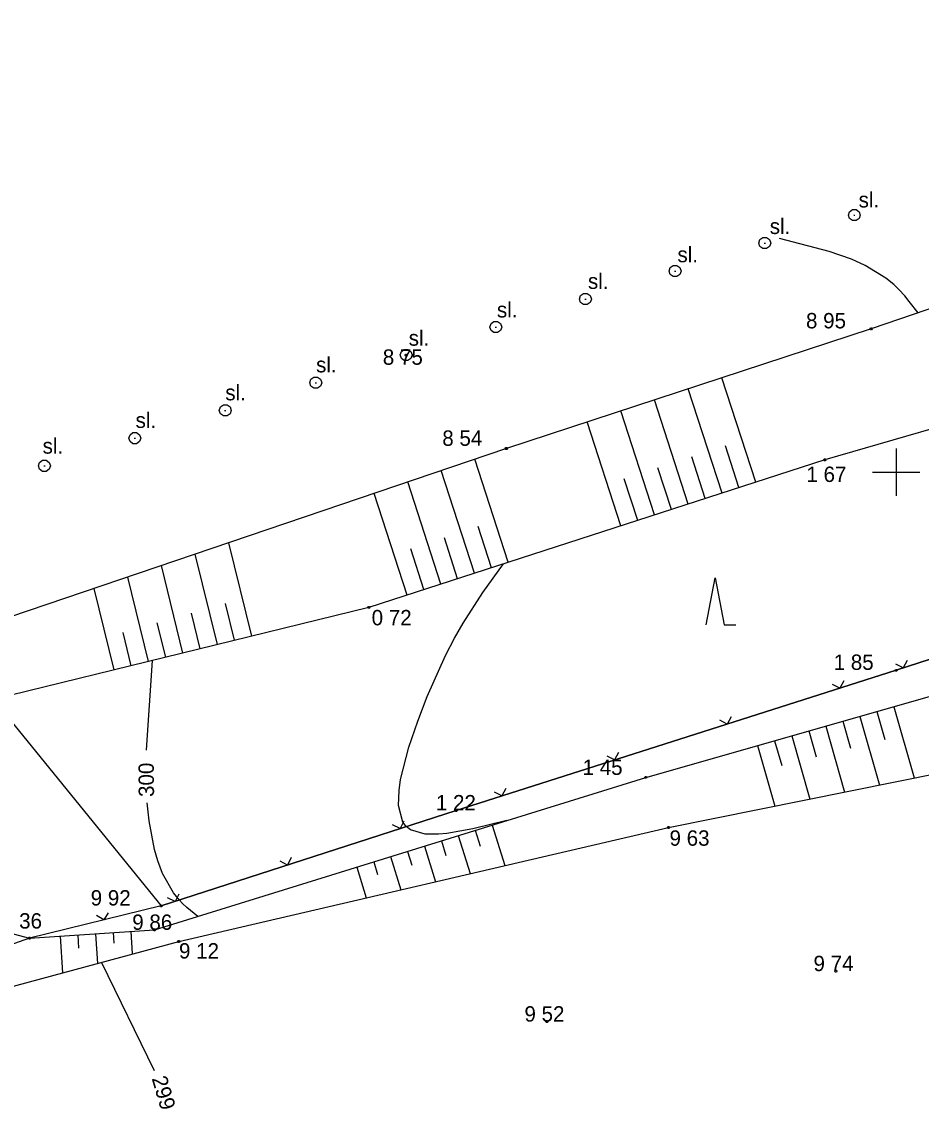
# Model space of a CAD drawing. Extents: x -684336 to -684039, y -993109 to -992688.
# Drawn here: x -684236.99 to -684198.94, y -992826.95 to -992780.95 of the extents above; entities that cross this region are included whole.
import ezdxf

# ---------------------------------------------------------------- set-up
doc = ezdxf.new("R2010")
doc.units = 0
for name, color, linetype in [('51', 7, 'Continuous'), ('53', 7, 'Continuous'), ('55', 7, 'Continuous'), ('56', 7, 'Continuous'), ('57', 7, 'Continuous'), ('60', 7, 'Continuous'), ('70', 7, 'Continuous'), ('81', 7, 'Continuous')]:
    doc.layers.add(name, color=color, linetype=linetype)

msp = doc.modelspace()

# ---------------------------------------------------------------- linework, layer by layer
at = {"layer": '51'}
for points in [[(-684153.498, -992795.02), (-684158.4, -992796.16), (-684158.08, -992789.98), (-684162.97, -992785.34), (-684173.37, -992785.88), (-684187.14, -992789.19), (-684201.06, -992793.94), (-684216.49, -992799), (-684239.84, -992806.93)], [(-684155.696, -992787.999), (-684158.08, -992789.98), (-684161.21, -992793.24), (-684163.83, -992796.06), (-684166.91, -992797.89), (-684183.05, -992802.89), (-684200, -992808.38), (-684218.61, -992814.31), (-684231.09, -992818.35), (-684236.66, -992819.71), (-684248.11, -992823.77)], [(-684161.21, -992793.24), (-684163.51, -992789.57), (-684179.03, -992792.54), (-684203.02, -992799.48), (-684222.3, -992805.72), (-684238.2, -992809.62), (-684250.775, -992812.098)], [(-684251.105, -992813.042), (-684244.68, -992817.58), (-684236.66, -992819.71), (-684231.37, -992819.36), (-684210.59, -992812.91), (-684194.44, -992808.31), (-684190.16, -992807.38), (-684180.44, -992804.41), (-684173.82, -992803.72), (-684160.95, -992797.464)], [(-684242.63, -992823.16), (-684230.34, -992819.85), (-684209.63, -992815.03), (-684188.57, -992810.79), (-684181.93, -992807.38), (-684170.95, -992804.67), (-684162.34, -992803.75), (-684152.61, -992807.1), (-684146.61, -992817.325)], [(-684199.538, -992807.967), (-684199.699, -992808.282), (-684200.013, -992808.122)], [(-684202.22, -992808.825), (-684202.382, -992809.139), (-684202.696, -992808.977)], [(-684206.984, -992810.343), (-684207.146, -992810.657), (-684207.46, -992810.495)], [(-684211.748, -992811.861), (-684211.91, -992812.175), (-684212.224, -992812.013)], [(-684216.512, -992813.379), (-684216.674, -992813.693), (-684216.988, -992813.531)], [(-684220.828, -992814.765), (-684220.988, -992815.08), (-684221.303, -992814.919)], [(-684225.585, -992816.305), (-684225.745, -992816.62), (-684226.06, -992816.459)], [(-684230.342, -992817.845), (-684230.502, -992818.16), (-684230.817, -992817.999)], [(-684233.335, -992818.641), (-684233.519, -992818.943), (-684233.821, -992818.759)]]:
    msp.add_lwpolyline(points, dxfattribs=at)
at = {"layer": '53'}
for points in [[(-684200, -992799), (-684200, -992801)], [(-684201, -992800), (-684199, -992800)]]:
    msp.add_lwpolyline(points, dxfattribs=at)
at = {"layer": '55'}
for points in [[(-684201.692, -992788.893), (-684201.567, -992788.983), (-684201.517, -992789.128), (-684201.567, -992789.273), (-684201.692, -992789.363), (-684201.847, -992789.363), (-684201.972, -992789.273), (-684202.022, -992789.128), (-684201.972, -992788.983), (-684201.847, -992788.893)], [(-684205.483, -992790.077), (-684205.358, -992790.167), (-684205.308, -992790.312), (-684205.358, -992790.457), (-684205.483, -992790.547), (-684205.638, -992790.547), (-684205.763, -992790.457), (-684205.813, -992790.312), (-684205.763, -992790.167), (-684205.638, -992790.077)], [(-684209.275, -992791.26), (-684209.15, -992791.35), (-684209.1, -992791.495), (-684209.15, -992791.64), (-684209.275, -992791.73), (-684209.43, -992791.73), (-684209.555, -992791.64), (-684209.605, -992791.495), (-684209.555, -992791.35), (-684209.43, -992791.26)], [(-684213.067, -992792.443), (-684212.942, -992792.533), (-684212.892, -992792.678), (-684212.942, -992792.823), (-684213.067, -992792.913), (-684213.222, -992792.913), (-684213.347, -992792.823), (-684213.397, -992792.678), (-684213.347, -992792.533), (-684213.222, -992792.443)], [(-684216.858, -992793.627), (-684216.733, -992793.717), (-684216.683, -992793.862), (-684216.733, -992794.007), (-684216.858, -992794.097), (-684217.013, -992794.097), (-684217.138, -992794.007), (-684217.188, -992793.862), (-684217.138, -992793.717), (-684217.013, -992793.627)], [(-684220.65, -992794.81), (-684220.525, -992794.9), (-684220.475, -992795.045), (-684220.525, -992795.19), (-684220.65, -992795.28), (-684220.805, -992795.28), (-684220.93, -992795.19), (-684220.98, -992795.045), (-684220.93, -992794.9), (-684220.805, -992794.81)], [(-684224.476, -992795.982), (-684224.351, -992796.072), (-684224.301, -992796.217), (-684224.351, -992796.362), (-684224.476, -992796.452), (-684224.631, -992796.452), (-684224.756, -992796.362), (-684224.806, -992796.217), (-684224.756, -992796.072), (-684224.631, -992795.982)], [(-684228.302, -992797.154), (-684228.177, -992797.244), (-684228.127, -992797.389), (-684228.177, -992797.534), (-684228.302, -992797.624), (-684228.457, -992797.624), (-684228.582, -992797.534), (-684228.632, -992797.389), (-684228.582, -992797.244), (-684228.457, -992797.154)], [(-684232.128, -992798.326), (-684232.003, -992798.416), (-684231.953, -992798.561), (-684232.003, -992798.706), (-684232.128, -992798.796), (-684232.283, -992798.796), (-684232.408, -992798.706), (-684232.458, -992798.561), (-684232.408, -992798.416), (-684232.283, -992798.326)], [(-684235.954, -992799.498), (-684235.829, -992799.588), (-684235.779, -992799.733), (-684235.829, -992799.878), (-684235.954, -992799.968), (-684236.109, -992799.968), (-684236.234, -992799.878), (-684236.284, -992799.733), (-684236.234, -992799.588), (-684236.109, -992799.498)]]:
    msp.add_lwpolyline(points, close=True, dxfattribs=at)
for points in [[(-684201.797, -992789.133), (-684201.742, -992789.133)], [(-684205.588, -992790.317), (-684205.533, -992790.317)], [(-684209.38, -992791.5), (-684209.325, -992791.5)], [(-684213.172, -992792.683), (-684213.117, -992792.683)], [(-684216.963, -992793.867), (-684216.908, -992793.867)], [(-684220.755, -992795.05), (-684220.7, -992795.05)], [(-684224.581, -992796.222), (-684224.526, -992796.222)], [(-684228.407, -992797.394), (-684228.352, -992797.394)], [(-684232.233, -992798.566), (-684232.178, -992798.566)], [(-684236.059, -992799.738), (-684236.004, -992799.738)]]:
    msp.add_lwpolyline(points, dxfattribs=at)
at = {"layer": '57'}
for points in [[(-684201.038, -992793.902), (-684201.015, -992793.94), (-684201.038, -992793.977), (-684201.083, -992793.977), (-684201.105, -992793.94), (-684201.083, -992793.902)], [(-684220.708, -992795.013), (-684220.685, -992795.05), (-684220.708, -992795.088), (-684220.753, -992795.088), (-684220.775, -992795.05), (-684220.753, -992795.013)], [(-684216.468, -992798.963), (-684216.445, -992799), (-684216.468, -992799.037), (-684216.513, -992799.037), (-684216.535, -992799), (-684216.513, -992798.963)], [(-684202.998, -992799.443), (-684202.975, -992799.48), (-684202.998, -992799.518), (-684203.042, -992799.518), (-684203.065, -992799.48), (-684203.042, -992799.443)], [(-684222.278, -992805.682), (-684222.255, -992805.72), (-684222.278, -992805.758), (-684222.323, -992805.758), (-684222.345, -992805.72), (-684222.323, -992805.682)], [(-684199.978, -992808.343), (-684199.955, -992808.38), (-684199.978, -992808.417), (-684200.022, -992808.417), (-684200.045, -992808.38), (-684200.022, -992808.343)], [(-684210.568, -992812.873), (-684210.545, -992812.91), (-684210.568, -992812.948), (-684210.613, -992812.948), (-684210.635, -992812.91), (-684210.613, -992812.873)], [(-684218.588, -992814.273), (-684218.565, -992814.31), (-684218.588, -992814.348), (-684218.633, -992814.348), (-684218.655, -992814.31), (-684218.633, -992814.273)], [(-684209.608, -992814.992), (-684209.585, -992815.03), (-684209.608, -992815.068), (-684209.653, -992815.068), (-684209.675, -992815.03), (-684209.653, -992814.992)], [(-684231.068, -992818.312), (-684231.045, -992818.35), (-684231.068, -992818.388), (-684231.113, -992818.388), (-684231.135, -992818.35), (-684231.113, -992818.312)], [(-684236.638, -992819.672), (-684236.615, -992819.71), (-684236.638, -992819.747), (-684236.682, -992819.747), (-684236.705, -992819.71), (-684236.682, -992819.672)], [(-684231.347, -992819.323), (-684231.325, -992819.36), (-684231.347, -992819.397), (-684231.392, -992819.397), (-684231.415, -992819.36), (-684231.392, -992819.323)], [(-684230.318, -992819.812), (-684230.295, -992819.85), (-684230.318, -992819.888), (-684230.363, -992819.888), (-684230.385, -992819.85), (-684230.363, -992819.812)], [(-684202.531, -992821.069), (-684202.508, -992821.106), (-684202.531, -992821.144), (-684202.576, -992821.144), (-684202.598, -992821.106), (-684202.576, -992821.069)], [(-684214.758, -992823.202), (-684214.735, -992823.24), (-684214.758, -992823.277), (-684214.802, -992823.277), (-684214.825, -992823.24), (-684214.802, -992823.202)]]:
    msp.add_lwpolyline(points, close=True, dxfattribs=at)
at = {"layer": '60'}
for points in [[(-684289.52, -992807.91), (-684276.43, -992803.58), (-684264.11, -992808.42), (-684259.07, -992805.67), (-684239.84, -992806.93), (-684238.2, -992809.62), (-684231.09, -992818.35), (-684218.61, -992814.31), (-684200, -992808.38), (-684183.05, -992802.89), (-684179.03, -992792.54), (-684175.03, -992780.95)], [(-684208.032, -992806.465), (-684207.657, -992804.465), (-684207.282, -992806.465), (-684206.782, -992806.465)]]:
    msp.add_lwpolyline(points, dxfattribs=at)
at = {"layer": '70'}
for points in [[(-684205.939, -992800.425), (-684207.368, -992796.009)], [(-684207.366, -992800.887), (-684208.793, -992796.476)], [(-684208.793, -992801.348), (-684210.219, -992796.943)], [(-684210.22, -992801.81), (-684211.644, -992797.411)], [(-684211.647, -992802.272), (-684213.069, -992797.878)], [(-684206.652, -992800.656), (-684207.224, -992798.89)], [(-684216.409, -992803.813), (-684217.821, -992799.452)], [(-684208.079, -992801.118), (-684208.65, -992799.354)], [(-684217.836, -992804.275), (-684219.241, -992799.934)], [(-684209.507, -992801.579), (-684210.077, -992799.818)], [(-684219.263, -992804.737), (-684220.662, -992800.417)], [(-684210.934, -992802.041), (-684211.503, -992800.283)], [(-684220.691, -992805.199), (-684222.082, -992800.899)], [(-684217.123, -992804.044), (-684217.686, -992802.304)], [(-684227.256, -992806.936), (-684228.225, -992802.985)], [(-684218.55, -992804.506), (-684219.111, -992802.774)], [(-684228.713, -992807.293), (-684229.651, -992803.47)], [(-684219.977, -992804.968), (-684220.535, -992803.244)], [(-684230.17, -992807.65), (-684231.076, -992803.954)], [(-684231.626, -992808.008), (-684232.502, -992804.438)], [(-684233.083, -992808.365), (-684233.928, -992804.922)], [(-684227.984, -992807.114), (-684228.366, -992805.56)], [(-684230.898, -992807.829), (-684231.254, -992806.376)], [(-684229.441, -992807.472), (-684229.81, -992805.968)], [(-684232.355, -992808.186), (-684232.699, -992806.784)], [(-684200.092, -992809.92), (-684199.232, -992812.937)], [(-684202.256, -992810.536), (-684201.931, -992811.675)], [(-684201.534, -992810.331), (-684200.707, -992813.234)], [(-684200.813, -992810.125), (-684200.476, -992811.309)], [(-684203.698, -992810.947), (-684203.387, -992812.04)], [(-684202.977, -992810.742), (-684202.182, -992813.531)], [(-684205.141, -992811.358), (-684204.843, -992812.405)], [(-684204.419, -992811.152), (-684203.658, -992813.828)], [(-684205.862, -992811.563), (-684205.133, -992814.125)], [(-684217.804, -992815.149), (-684217.598, -992815.815)], [(-684217.088, -992814.927), (-684216.556, -992816.642)], [(-684219.237, -992815.594), (-684219.043, -992816.218)], [(-684218.521, -992815.372), (-684218.021, -992816.983)], [(-684220.67, -992816.039), (-684220.489, -992816.621)], [(-684219.953, -992815.816), (-684219.485, -992817.324)], [(-684222.102, -992816.483), (-684221.934, -992817.024)], [(-684221.386, -992816.261), (-684220.95, -992817.665)], [(-684222.818, -992816.706), (-684222.415, -992818.006)], [(-684235.369, -992819.625), (-684235.266, -992821.177)], [(-684234.621, -992819.575), (-684234.583, -992820.136)], [(-684233.872, -992819.526), (-684233.789, -992820.779)], [(-684233.124, -992819.476), (-684233.095, -992819.918)], [(-684232.375, -992819.427), (-684232.312, -992820.381)]]:
    msp.add_lwpolyline(points, dxfattribs=at)
at = {"layer": '81'}
for points in [[(-684199.071, -992793.261), (-684199.444, -992792.779), (-684199.638, -992792.546), (-684199.881, -992792.278), (-684200.098, -992792.068), (-684200.433, -992791.792), (-684201.307, -992791.262), (-684201.895, -992790.998), (-684202.838, -992790.667), (-684204.931, -992790.119)], [(-684216.471, -992814.735), (-684217.907, -992815.088), (-684219.004, -992815.284), (-684219.357, -992815.317), (-684219.925, -992815.31), (-684220.543, -992815.131), (-684220.722, -992814.994), (-684220.87, -992814.8), (-684221.05, -992814.107), (-684221.029, -992813.465), (-684220.961, -992813.004), (-684220.609, -992811.631), (-684220.234, -992810.53), (-684219.835, -992809.489), (-684219.065, -992807.762), (-684218.679, -992807.017), (-684218.323, -992806.389), (-684217.484, -992805.084), (-684216.617, -992803.881)], [(-684231.715, -992811.763), (-684231.458, -992807.966)], [(-684229.54, -992818.792), (-684229.853, -992818.54), (-684230.006, -992818.409), (-684230.182, -992818.246), (-684230.322, -992818.101), (-684230.573, -992817.792), (-684231.033, -992816.976), (-684231.237, -992816.44), (-684231.379, -992815.956), (-684231.605, -992814.746), (-684231.68, -992813.991)], [(-684231.369, -992825.324), (-684233.617, -992820.733)]]:
    msp.add_lwpolyline(points, dxfattribs=at)

# ---------------------------------------------------------------- texts
at = {"layer": '56'}
for p in [(-684201.588, -992788.806), (-684205.347, -992789.927), (-684209.252, -992791.122), (-684213.037, -992792.25), (-684216.888, -992793.458), (-684220.62, -992794.653), (-684224.538, -992795.781), (-684228.377, -992796.962), (-684232.175, -992798.13), (-684236.106, -992799.218)]:
    msp.add_text('sl.', height=0.65, dxfattribs=at).set_placement(p)
at = {"layer": '57'}
for s, p in [('8 95', (-684203.814, -992793.919)), ('8 75', (-684221.715, -992795.458)), ('8 54', (-684219.199, -992798.887)), ('1 67', (-684203.796, -992800.416)), ('0 72', (-684222.187, -992806.479)), ('1 85', (-684202.644, -992808.365)), ('1 45', (-684213.265, -992812.807)), ('1 22', (-684219.471, -992814.307)), ('9 63', (-684209.587, -992815.802)), ('9 92', (-684234.072, -992818.331)), ('9 36', (-684237.823, -992819.305)), ('9 86', (-684232.314, -992819.36)), ('9 12', (-684230.336, -992820.572)), ('9 74', (-684203.497, -992821.106)), ('9 52', (-684215.724, -992823.24))]:
    msp.add_text(s, height=0.65, dxfattribs=at).set_placement(p)
at = {"layer": '81'}
for s, rotation, p in [('300', 90.4234, (-684231.392, -992813.737)), ('299', 286.3643, (-684231.496, -992825.644))]:
    msp.add_text(s, height=0.65, rotation=rotation, dxfattribs=at).set_placement(p)

doc.saveas('drawing.dxf')
